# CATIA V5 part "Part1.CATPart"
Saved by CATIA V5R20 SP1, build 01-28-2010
Part number: Part1
Bounding box of the stored display mesh (mm): x 0 to 23.455, y 0 to 0, z 45 to 63.705
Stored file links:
  C:\Users\Matthieu\Desktop\IAO_2012_mcamard_Catia\Part1.CATPart
  C:\Users\Matthieu\Desktop\IAO_2012_mcamard_Catia\mcamard.CATProduct
  C:\Users\Matthieu\Desktop\IAO_2012_mcamard_Catia\piece_EA.CATPart
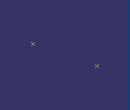
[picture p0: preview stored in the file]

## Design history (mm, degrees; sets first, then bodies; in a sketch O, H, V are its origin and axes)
Point1 "E": linked copy from another document
Point2 "A": linked copy from another document
Body1 (main body)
